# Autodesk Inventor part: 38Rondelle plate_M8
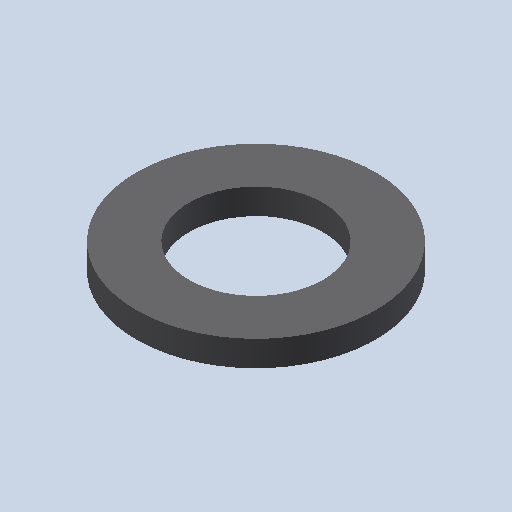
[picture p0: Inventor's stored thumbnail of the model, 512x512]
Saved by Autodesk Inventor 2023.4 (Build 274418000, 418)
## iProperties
Created: 2011-01
Part Number: 38Rondelle plate_M8
Document SubType Name: Modeling
Designer: eric
Density: 1 g/cm^3
Mass: 0.194075 g
Surface Area: 3.60215 cm^2
Volume: 0.194075 cm^3
Material: Générique
Appearance: Blue
Author: eric
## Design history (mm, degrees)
feature "Base1"
node "Corps solides"
node "Corps surfaciques"
node "Solide1"
